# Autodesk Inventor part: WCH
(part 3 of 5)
hole "Díra1365" diameter "d12284" = 2.19608; stored, may be unused: countersink angle "d12288" = 90 deg, drill point angle "d12290" = 0 deg; dims "d12282" = 241, "d12283" = 153, "d12285" = 6, "d12286" = 4, "d12287" = 2, "d12289" = 8
hole "Díra1366" diameter "d12293" = 6.27451; stored, may be unused: countersink angle "d12297" = 90 deg, drill point angle "d12299" = 0 deg; dims "d12291" = 252, "d12292" = 153, "d12294" = 6, "d12295" = 4, "d12296" = 2, "d12298" = 8
hole "Díra1367" diameter "d12302" = 5.80392; stored, may be unused: countersink angle "d12306" = 90 deg, drill point angle "d12308" = 0 deg; dims "d12300" = 263, "d12301" = 153, "d12303" = 6, "d12304" = 4, "d12305" = 2, "d12307" = 8
hole "Díra1368" diameter "d12311" = 2.70588; stored, may be unused: countersink angle "d12315" = 90 deg, drill point angle "d12317" = 0 deg; dims "d12309" = 274, "d12310" = 153, "d12312" = 6, "d12313" = 4, "d12314" = 2, "d12316" = 8
hole "Díra1369" diameter "d12320" = 1.09804; stored, may be unused: countersink angle "d12324" = 90 deg, drill point angle "d12326" = 0 deg; dims "d12318" = 285, "d12319" = 153, "d12321" = 6, "d12322" = 4, "d12323" = 2, "d12325" = 8
hole "Díra1370" diameter "d12329" = 2.07843; stored, may be unused: countersink angle "d12333" = 90 deg, drill point angle "d12335" = 0 deg; dims "d12327" = 296, "d12328" = 153, "d12330" = 6, "d12331" = 4, "d12332" = 2, "d12334" = 8
hole "Díra1371" diameter "d12338" = 1.01961; stored, may be unused: countersink angle "d12342" = 90 deg, drill point angle "d12344" = 0 deg; dims "d12336" = 307, "d12337" = 153, "d12339" = 6, "d12340" = 4, "d12341" = 2, "d12343" = 8
hole "Díra1372" diameter "d12347" = 0.75817; stored, may be unused: countersink angle "d12351" = 90 deg, drill point angle "d12353" = 0 deg; dims "d12345" = 318, "d12346" = 153, "d12348" = 6, "d12349" = 4, "d12350" = 2, "d12352" = 8
hole "Díra1373" diameter "d12356" = 0.82353; stored, may be unused: countersink angle "d12360" = 90 deg, drill point angle "d12362" = 0 deg; dims "d12354" = 329, "d12355" = 153, "d12357" = 6, "d12358" = 4, "d12359" = 2, "d12361" = 8
hole "Díra1374" diameter "d12365" = 1.33333; stored, may be unused: countersink angle "d12369" = 90 deg, drill point angle "d12371" = 0 deg; dims "d12363" = 340, "d12364" = 153, "d12366" = 6, "d12367" = 4, "d12368" = 2, "d12370" = 8
hole "Díra1375" diameter "d12374" = 1.88235; stored, may be unused: countersink angle "d12378" = 90 deg, drill point angle "d12380" = 0 deg; dims "d12372" = 351, "d12373" = 153, "d12375" = 6, "d12376" = 4, "d12377" = 2, "d12379" = 8
hole "Díra1376" diameter "d12383" = 3.41176; stored, may be unused: countersink angle "d12387" = 90 deg, drill point angle "d12389" = 0 deg; dims "d12381" = 10, "d12382" = 164, "d12384" = 6, "d12385" = 4, "d12386" = 2, "d12388" = 8
hole "Díra1377" diameter "d12392" = 3.17647; stored, may be unused: countersink angle "d12396" = 90 deg, drill point angle "d12398" = 0 deg; dims "d12390" = 21, "d12391" = 164, "d12393" = 6, "d12394" = 4, "d12395" = 2, "d12397" = 8
hole "Díra1378" diameter "d12401" = 2.27451; stored, may be unused: countersink angle "d12405" = 90 deg, drill point angle "d12407" = 0 deg; dims "d12399" = 32, "d12400" = 164, "d12402" = 6, "d12403" = 4, "d12404" = 2, "d12406" = 8
hole "Díra1379" diameter "d12410" = 4.78431; stored, may be unused: countersink angle "d12414" = 90 deg, drill point angle "d12416" = 0 deg; dims "d12408" = 43, "d12409" = 164, "d12411" = 6, "d12412" = 4, "d12413" = 2, "d12415" = 8
hole "Díra1380" diameter "d12419" = 8.82353; stored, may be unused: countersink angle "d12423" = 90 deg, drill point angle "d12425" = 0 deg; dims "d12417" = 54, "d12418" = 164, "d12420" = 6, "d12421" = 4, "d12422" = 2, "d12424" = 8
hole "Díra1381" diameter "d12428" = 5.64706; stored, may be unused: countersink angle "d12432" = 90 deg, drill point angle "d12434" = 0 deg; dims "d12426" = 65, "d12427" = 164, "d12429" = 6, "d12430" = 4, "d12431" = 2, "d12433" = 8
hole "Díra1382" diameter "d12437" = 10; stored, may be unused: countersink angle "d12441" = 90 deg, drill point angle "d12443" = 0 deg; dims "d12435" = 76, "d12436" = 164, "d12438" = 6, "d12439" = 4, "d12440" = 2, "d12442" = 8
hole "Díra1383" diameter "d12446" = 8.54902; stored, may be unused: countersink angle "d12450" = 90 deg, drill point angle "d12452" = 0 deg; dims "d12444" = 87, "d12445" = 164, "d12447" = 6, "d12448" = 4, "d12449" = 2, "d12451" = 8
hole "Díra1384" diameter "d12455" = 2.47059; stored, may be unused: countersink angle "d12459" = 90 deg, drill point angle "d12461" = 0 deg; dims "d12453" = 98, "d12454" = 164, "d12456" = 6, "d12457" = 4, "d12458" = 2, "d12460" = 8
hole "Díra1385" diameter "d12464" = 2.94118; stored, may be unused: countersink angle "d12468" = 90 deg, drill point angle "d12470" = 0 deg; dims "d12462" = 109, "d12463" = 164, "d12465" = 6, "d12466" = 4, "d12467" = 2, "d12469" = 8
hole "Díra1386" diameter "d12473" = 4; stored, may be unused: countersink angle "d12477" = 90 deg, drill point angle "d12479" = 0 deg; dims "d12471" = 120, "d12472" = 164, "d12474" = 6, "d12475" = 4, "d12476" = 2, "d12478" = 8
hole "Díra1387" diameter "d12482" = 5.41177; stored, may be unused: countersink angle "d12486" = 90 deg, drill point angle "d12488" = 0 deg; dims "d12480" = 131, "d12481" = 164, "d12483" = 6, "d12484" = 4, "d12485" = 2, "d12487" = 8
hole "Díra1388" diameter "d12491" = 5.41177; stored, may be unused: countersink angle "d12495" = 90 deg, drill point angle "d12497" = 0 deg; dims "d12489" = 142, "d12490" = 164, "d12492" = 6, "d12493" = 4, "d12494" = 2, "d12496" = 8
hole "Díra1389" diameter "d12500" = 5.29412; stored, may be unused: countersink angle "d12504" = 90 deg, drill point angle "d12506" = 0 deg; dims "d12498" = 153, "d12499" = 164, "d12501" = 6, "d12502" = 4, "d12503" = 2, "d12505" = 8
hole "Díra1390" diameter "d12509" = 6.66667; stored, may be unused: countersink angle "d12513" = 90 deg, drill point angle "d12515" = 0 deg; dims "d12507" = 164, "d12508" = 164, "d12510" = 6, "d12511" = 4, "d12512" = 2, "d12514" = 8
hole "Díra1391" diameter "d12518" = 5.05882; stored, may be unused: countersink angle "d12522" = 90 deg, drill point angle "d12524" = 0 deg; dims "d12516" = 175, "d12517" = 164, "d12519" = 6, "d12520" = 4, "d12521" = 2, "d12523" = 8
hole "Díra1392" diameter "d12527" = 5.4902; stored, may be unused: countersink angle "d12531" = 90 deg, drill point angle "d12533" = 0 deg; dims "d12525" = 186, "d12526" = 164, "d12528" = 6, "d12529" = 4, "d12530" = 2, "d12532" = 8
hole "Díra1393" diameter "d12536" = 6.7451; stored, may be unused: countersink angle "d12540" = 90 deg, drill point angle "d12542" = 0 deg; dims "d12534" = 197, "d12535" = 164, "d12537" = 6, "d12538" = 4, "d12539" = 2, "d12541" = 8
hole "Díra1394" diameter "d12545" = 6.07843; stored, may be unused: countersink angle "d12549" = 90 deg, drill point angle "d12551" = 0 deg; dims "d12543" = 208, "d12544" = 164, "d12546" = 6, "d12547" = 4, "d12548" = 2, "d12550" = 8
hole "Díra1395" diameter "d12554" = 6.78431; stored, may be unused: countersink angle "d12558" = 90 deg, drill point angle "d12560" = 0 deg; dims "d12552" = 219, "d12553" = 164, "d12555" = 6, "d12556" = 4, "d12557" = 2, "d12559" = 8
hole "Díra1396" diameter "d12563" = 6.5098; stored, may be unused: countersink angle "d12567" = 90 deg, drill point angle "d12569" = 0 deg; dims "d12561" = 230, "d12562" = 164, "d12564" = 6, "d12565" = 4, "d12566" = 2, "d12568" = 8
hole "Díra1397" diameter "d12572" = 5.68628; stored, may be unused: countersink angle "d12576" = 90 deg, drill point angle "d12578" = 0 deg; dims "d12570" = 241, "d12571" = 164, "d12573" = 6, "d12574" = 4, "d12575" = 2, "d12577" = 8
hole "Díra1398" diameter "d12581" = 4.48366; stored, may be unused: countersink angle "d12585" = 90 deg, drill point angle "d12587" = 0 deg; dims "d12579" = 252, "d12580" = 164, "d12582" = 6, "d12583" = 4, "d12584" = 2, "d12586" = 8
hole "Díra1399" diameter "d12590" = 3.37255; stored, may be unused: countersink angle "d12594" = 90 deg, drill point angle "d12596" = 0 deg; dims "d12588" = 263, "d12589" = 164, "d12591" = 6, "d12592" = 4, "d12593" = 2, "d12595" = 8
hole "Díra1400" diameter "d12599" = 1.72549; stored, may be unused: countersink angle "d12603" = 90 deg, drill point angle "d12605" = 0 deg; dims "d12597" = 274, "d12598" = 164, "d12600" = 6, "d12601" = 4, "d12602" = 2, "d12604" = 8
hole "Díra1401" diameter "d12608" = 0.07843; stored, may be unused: countersink angle "d12612" = 90 deg, drill point angle "d12614" = 0 deg; dims "d12606" = 318, "d12607" = 164, "d12609" = 6, "d12610" = 4, "d12611" = 2, "d12613" = 8
hole "Díra1402" diameter "d12617" = 0.5098; stored, may be unused: countersink angle "d12621" = 90 deg, drill point angle "d12623" = 0 deg; dims "d12615" = 329, "d12616" = 164, "d12618" = 6, "d12619" = 4, "d12620" = 2, "d12622" = 8
hole "Díra1403" diameter "d12626" = 0.78431; stored, may be unused: countersink angle "d12630" = 90 deg, drill point angle "d12632" = 0 deg; dims "d12624" = 340, "d12625" = 164, "d12627" = 6, "d12628" = 4, "d12629" = 2, "d12631" = 8
hole "Díra1404" diameter "d12635" = 1.33333; stored, may be unused: countersink angle "d12639" = 90 deg, drill point angle "d12641" = 0 deg; dims "d12633" = 351, "d12634" = 164, "d12636" = 6, "d12637" = 4, "d12638" = 2, "d12640" = 8
hole "Díra1405" diameter "d12644" = 3.80392; stored, may be unused: countersink angle "d12648" = 90 deg, drill point angle "d12650" = 0 deg; dims "d12642" = 10, "d12643" = 175, "d12645" = 6, "d12646" = 4, "d12647" = 2, "d12649" = 8
hole "Díra1406" diameter "d12653" = 3.76471; stored, may be unused: countersink angle "d12657" = 90 deg, drill point angle "d12659" = 0 deg; dims "d12651" = 21, "d12652" = 175, "d12654" = 6, "d12655" = 4, "d12656" = 2, "d12658" = 8
hole "Díra1407" diameter "d12662" = 2.7451; stored, may be unused: countersink angle "d12666" = 90 deg, drill point angle "d12668" = 0 deg; dims "d12660" = 32, "d12661" = 175, "d12663" = 6, "d12664" = 4, "d12665" = 2, "d12667" = 8
hole "Díra1408" diameter "d12671" = 3.60784; stored, may be unused: countersink angle "d12675" = 90 deg, drill point angle "d12677" = 0 deg; dims "d12669" = 43, "d12670" = 175, "d12672" = 6, "d12673" = 4, "d12674" = 2, "d12676" = 8
hole "Díra1409" diameter "d12680" = 6.47059; stored, may be unused: countersink angle "d12684" = 90 deg, drill point angle "d12686" = 0 deg, countersink angle "d14007" = 90 deg; dims "d12678" = 54, "d12679" = 175, "d12681" = 6, "d12682" = 4, "d12683" = 2, "d12685" = 8
hole "Díra1410" diameter "d12689" = 8.43137; stored, may be unused: countersink angle "d12693" = 90 deg, drill point angle "d12695" = 0 deg; dims "d12687" = 65, "d12688" = 175, "d12690" = 6, "d12691" = 4, "d12692" = 2, "d12694" = 8, "d16117" = 318
hole "Díra1411" diameter "d12698" = 10; stored, may be unused: countersink angle "d12702" = 90 deg, drill point angle "d12704" = 0 deg; dims "d12696" = 76, "d12697" = 175, "d12699" = 6, "d12700" = 4, "d12701" = 2, "d12703" = 8
hole "Díra1412" diameter "d12707" = 6.66667; stored, may be unused: countersink angle "d12711" = 90 deg, drill point angle "d12713" = 0 deg; dims "d12705" = 87, "d12706" = 175, "d12708" = 6, "d12709" = 4, "d12710" = 2, "d12712" = 8
hole "Díra1413" diameter "d12716" = 2.19608; stored, may be unused: countersink angle "d12720" = 90 deg, drill point angle "d12722" = 0 deg; dims "d12714" = 98, "d12715" = 175, "d12717" = 6, "d12718" = 4, "d12719" = 2, "d12721" = 8
hole "Díra1414" diameter "d12725" = 3.4902; stored, may be unused: countersink angle "d12729" = 90 deg, drill point angle "d12731" = 0 deg; dims "d12723" = 109, "d12724" = 175, "d12726" = 6, "d12727" = 4, "d12728" = 2, "d12730" = 8
hole "Díra1415" diameter "d12734" = 3.13726; stored, may be unused: countersink angle "d12738" = 90 deg, drill point angle "d12740" = 0 deg; dims "d12732" = 120, "d12733" = 175, "d12735" = 6, "d12736" = 4, "d12737" = 2, "d12739" = 8
hole "Díra1416" diameter "d12743" = 1.84314; stored, may be unused: countersink angle "d12747" = 90 deg, drill point angle "d12749" = 0 deg; dims "d12741" = 131, "d12742" = 175, "d12744" = 6, "d12745" = 4, "d12746" = 2, "d12748" = 8
hole "Díra1417" diameter "d12752" = 1.01961; stored, may be unused: countersink angle "d12756" = 90 deg, drill point angle "d12758" = 0 deg; dims "d12750" = 142, "d12751" = 175, "d12753" = 6, "d12754" = 4, "d12755" = 2, "d12757" = 8
hole "Díra1418" diameter "d12761" = 0.5098; stored, may be unused: countersink angle "d12765" = 90 deg, drill point angle "d12767" = 0 deg; dims "d12759" = 153, "d12760" = 175, "d12762" = 6, "d12763" = 4, "d12764" = 2, "d12766" = 8
hole "Díra1419" diameter "d12770" = 1.60784; stored, may be unused: countersink angle "d12774" = 90 deg, drill point angle "d12776" = 0 deg; dims "d12768" = 164, "d12769" = 175, "d12771" = 6, "d12772" = 4, "d12773" = 2, "d12775" = 8
hole "Díra1420" diameter "d12779" = 5.80392; stored, may be unused: countersink angle "d12783" = 90 deg, drill point angle "d12785" = 0 deg; dims "d12777" = 175, "d12778" = 175, "d12780" = 6, "d12781" = 4, "d12782" = 2, "d12784" = 8
hole "Díra1421" diameter "d12788" = 2.15686; stored, may be unused: countersink angle "d12792" = 90 deg, drill point angle "d12794" = 0 deg; dims "d12786" = 186, "d12787" = 175, "d12789" = 6, "d12790" = 4, "d12791" = 2, "d12793" = 8
hole "Díra1422" diameter "d12797" = 1.92157; stored, may be unused: countersink angle "d12801" = 90 deg, drill point angle "d12803" = 0 deg; dims "d12795" = 197, "d12796" = 175, "d12798" = 6, "d12799" = 4, "d12800" = 2, "d12802" = 8
hole "Díra1423" diameter "d12806" = 0.90196; stored, may be unused: countersink angle "d12810" = 90 deg, drill point angle "d12812" = 0 deg; dims "d12804" = 208, "d12805" = 175, "d12807" = 6, "d12808" = 4, "d12809" = 2, "d12811" = 8
hole "Díra1424" diameter "d12815" = 1.01961; stored, may be unused: countersink angle "d12819" = 90 deg, drill point angle "d12821" = 0 deg; dims "d12813" = 219, "d12814" = 175, "d12816" = 6, "d12817" = 4, "d12818" = 2, "d12820" = 8
hole "Díra1425" diameter "d12824" = 1.92157; stored, may be unused: countersink angle "d12828" = 90 deg, drill point angle "d12830" = 0 deg; dims "d12822" = 230, "d12823" = 175, "d12825" = 6, "d12826" = 4, "d12827" = 2, "d12829" = 8
hole "Díra1426" diameter "d12833" = 4.82353; stored, may be unused: countersink angle "d12837" = 90 deg, drill point angle "d12839" = 0 deg; dims "d12831" = 241, "d12832" = 175, "d12834" = 6, "d12835" = 4, "d12836" = 2, "d12838" = 8
hole "Díra1427" diameter "d12842" = 1.52941; stored, may be unused: countersink angle "d12846" = 90 deg, drill point angle "d12848" = 0 deg; dims "d12840" = 252, "d12841" = 175, "d12843" = 6, "d12844" = 4, "d12845" = 2, "d12847" = 8
hole "Díra1428" diameter "d12851" = 0.78431; stored, may be unused: countersink angle "d12855" = 90 deg, drill point angle "d12857" = 0 deg; dims "d12849" = 263, "d12850" = 175, "d12852" = 6, "d12853" = 4, "d12854" = 2, "d12856" = 8
hole "Díra1429" diameter "d12860" = 0.39216; stored, may be unused: countersink angle "d12864" = 90 deg, drill point angle "d12866" = 0 deg; dims "d12858" = 274, "d12859" = 175, "d12861" = 6, "d12862" = 4, "d12863" = 2, "d12865" = 8
hole "Díra1430" diameter "d12869" = 0.27451; stored, may be unused: countersink angle "d12873" = 90 deg, drill point angle "d12875" = 0 deg; dims "d12867" = 307, "d12868" = 175, "d12870" = 6, "d12871" = 4, "d12872" = 2, "d12874" = 8
hole "Díra1431" diameter "d12878" = 0.15686; stored, may be unused: countersink angle "d12882" = 90 deg, drill point angle "d12884" = 0 deg; dims "d12876" = 340, "d12877" = 175, "d12879" = 6, "d12880" = 4, "d12881" = 2, "d12883" = 8
hole "Díra1432" diameter "d12887" = 0.90196; stored, may be unused: countersink angle "d12891" = 90 deg, drill point angle "d12893" = 0 deg; dims "d12885" = 351, "d12886" = 175, "d12888" = 6, "d12889" = 4, "d12890" = 2, "d12892" = 8
hole "Díra1433" diameter "d12896" = 3.29412; stored, may be unused: countersink angle "d12900" = 90 deg, drill point angle "d12902" = 0 deg; dims "d12894" = 10, "d12895" = 186, "d12897" = 6, "d12898" = 4, "d12899" = 2, "d12901" = 8
hole "Díra1434" diameter "d12905" = 3.17647; stored, may be unused: countersink angle "d12909" = 90 deg, drill point angle "d12911" = 0 deg; dims "d12903" = 21, "d12904" = 186, "d12906" = 6, "d12907" = 4, "d12908" = 2, "d12910" = 8
hole "Díra1435" diameter "d12914" = 3.21569; stored, may be unused: countersink angle "d12918" = 90 deg, drill point angle "d12920" = 0 deg; dims "d12912" = 32, "d12913" = 186, "d12915" = 6, "d12916" = 4, "d12917" = 2, "d12919" = 8
hole "Díra1436" diameter "d12923" = 3.84314; stored, may be unused: countersink angle "d12927" = 90 deg, drill point angle "d12929" = 0 deg; dims "d12921" = 43, "d12922" = 186, "d12924" = 6, "d12925" = 4, "d12926" = 2, "d12928" = 8
hole "Díra1437" diameter "d12932" = 3.01961; stored, may be unused: countersink angle "d12936" = 90 deg, drill point angle "d12938" = 0 deg; dims "d12930" = 54, "d12931" = 186, "d12933" = 6, "d12934" = 4, "d12935" = 2, "d12937" = 8
hole "Díra1438" diameter "d12941" = 6.39216; stored, may be unused: countersink angle "d12945" = 90 deg, drill point angle "d12947" = 0 deg; dims "d12939" = 65, "d12940" = 186, "d12942" = 6, "d12943" = 4, "d12944" = 2, "d12946" = 8
hole "Díra1439" diameter "d12950" = 7.52941; stored, may be unused: countersink angle "d12954" = 90 deg, drill point angle "d12956" = 0 deg; dims "d12948" = 76, "d12949" = 186, "d12951" = 6, "d12952" = 4, "d12953" = 2, "d12955" = 8
hole "Díra1440" diameter "d12959" = 2.77124; stored, may be unused: countersink angle "d12963" = 90 deg, drill point angle "d12965" = 0 deg; dims "d12957" = 87, "d12958" = 186, "d12960" = 6, "d12961" = 4, "d12962" = 2, "d12964" = 8
hole "Díra1441" diameter "d12968" = 2.66667; stored, may be unused: countersink angle "d12972" = 90 deg, drill point angle "d12974" = 0 deg; dims "d12966" = 98, "d12967" = 186, "d12969" = 6, "d12970" = 4, "d12971" = 2, "d12973" = 8
hole "Díra1442" diameter "d12977" = 4.27451; stored, may be unused: countersink angle "d12981" = 90 deg, drill point angle "d12983" = 0 deg; dims "d12975" = 109, "d12976" = 186, "d12978" = 6, "d12979" = 4, "d12980" = 2, "d12982" = 8
hole "Díra1443" diameter "d12986" = 4.35294; stored, may be unused: countersink angle "d12990" = 90 deg, drill point angle "d12992" = 0 deg; dims "d12984" = 120, "d12985" = 186, "d12987" = 6, "d12988" = 4, "d12989" = 2, "d12991" = 8
hole "Díra1444" diameter "d12995" = 2.39216; stored, may be unused: countersink angle "d12999" = 90 deg, drill point angle "d13001" = 0 deg; dims "d12993" = 131, "d12994" = 186, "d12996" = 6, "d12997" = 4, "d12998" = 2, "d13000" = 8
hole "Díra1445" diameter "d13004" = 0.5098; stored, may be unused: countersink angle "d13008" = 90 deg, drill point angle "d13010" = 0 deg; dims "d13002" = 142, "d13003" = 186, "d13005" = 6, "d13006" = 4, "d13007" = 2, "d13009" = 8
hole "Díra1446" diameter "d13013" = 0.07843; stored, may be unused: countersink angle "d13017" = 90 deg, drill point angle "d13019" = 0 deg; dims "d13011" = 153, "d13012" = 186, "d13014" = 6, "d13015" = 4, "d13016" = 2, "d13018" = 8
hole "Díra1447" diameter "d13022" = 0.15686; stored, may be unused: countersink angle "d13026" = 90 deg, drill point angle "d13028" = 0 deg; dims "d13020" = 164, "d13021" = 186, "d13023" = 6, "d13024" = 4, "d13025" = 2, "d13027" = 8
hole "Díra1448" diameter "d13031" = 1.64706; stored, may be unused: countersink angle "d13035" = 90 deg, drill point angle "d13037" = 0 deg; dims "d13029" = 175, "d13030" = 186, "d13032" = 6, "d13033" = 4, "d13034" = 2, "d13036" = 8
hole "Díra1449" diameter "d13040" = 4; stored, may be unused: countersink angle "d13044" = 90 deg, drill point angle "d13046" = 0 deg; dims "d13038" = 186, "d13039" = 186, "d13041" = 6, "d13042" = 4, "d13043" = 2, "d13045" = 8
hole "Díra1450" diameter "d13049" = 2.90196; stored, may be unused: countersink angle "d13053" = 90 deg, drill point angle "d13055" = 0 deg; dims "d13047" = 197, "d13048" = 186, "d13050" = 6, "d13051" = 4, "d13052" = 2, "d13054" = 8
hole "Díra1451" diameter "d13058" = 0.27451; stored, may be unused: countersink angle "d13062" = 90 deg, drill point angle "d13064" = 0 deg; dims "d13056" = 208, "d13057" = 186, "d13059" = 6, "d13060" = 4, "d13061" = 2, "d13063" = 8
hole "Díra1452" diameter "d13067" = 3.52941; stored, may be unused: countersink angle "d13071" = 90 deg, drill point angle "d13073" = 0 deg; dims "d13065" = 230, "d13066" = 186, "d13068" = 6, "d13069" = 4, "d13070" = 2, "d13072" = 8
hole "Díra1453" diameter "d13076" = 3.76471; stored, may be unused: countersink angle "d13080" = 90 deg, drill point angle "d13082" = 0 deg; dims "d13074" = 241, "d13075" = 186, "d13077" = 6, "d13078" = 4, "d13079" = 2, "d13081" = 8
hole "Díra1454" diameter "d13085" = 0.78431; stored, may be unused: countersink angle "d13089" = 90 deg, drill point angle "d13091" = 0 deg; dims "d13083" = 252, "d13084" = 186, "d13086" = 6, "d13087" = 4, "d13088" = 2, "d13090" = 8
hole "Díra1455" diameter "d13094" = 0.43137; stored, may be unused: countersink angle "d13098" = 90 deg, drill point angle "d13100" = 0 deg; dims "d13092" = 263, "d13093" = 186, "d13095" = 6, "d13096" = 4, "d13097" = 2, "d13099" = 8
hole "Díra1456" diameter "d13103" = 1.01961; stored, may be unused: countersink angle "d13107" = 90 deg, drill point angle "d13109" = 0 deg; dims "d13101" = 274, "d13102" = 186, "d13104" = 6, "d13105" = 4, "d13106" = 2, "d13108" = 8
hole "Díra1457" diameter "d13112" = 0.19608; stored, may be unused: countersink angle "d13116" = 90 deg, drill point angle "d13118" = 0 deg; dims "d13110" = 285, "d13111" = 186, "d13113" = 6, "d13114" = 4, "d13115" = 2, "d13117" = 8
hole "Díra1458" diameter "d13121" = 0.31372; stored, may be unused: countersink angle "d13125" = 90 deg, drill point angle "d13127" = 0 deg; dims "d13119" = 296, "d13120" = 186, "d13122" = 6, "d13123" = 4, "d13124" = 2, "d13126" = 8
hole "Díra1459" diameter "d13130" = 3.01961; stored, may be unused: countersink angle "d13134" = 90 deg, drill point angle "d13136" = 0 deg; dims "d13128" = 307, "d13129" = 186, "d13131" = 6, "d13132" = 4, "d13133" = 2, "d13135" = 8
hole "Díra1460" diameter "d13139" = 2.19608; stored, may be unused: countersink angle "d13143" = 90 deg, drill point angle "d13145" = 0 deg; dims "d13137" = 318, "d13138" = 186, "d13140" = 6, "d13141" = 4, "d13142" = 2, "d13144" = 8
hole "Díra1461" diameter "d13148" = 3.4902; stored, may be unused: countersink angle "d13152" = 90 deg, drill point angle "d13154" = 0 deg; dims "d13146" = 10, "d13147" = 197, "d13149" = 6, "d13150" = 4, "d13151" = 2, "d13153" = 8
hole "Díra1462" diameter "d13157" = 3.37255; stored, may be unused: countersink angle "d13161" = 90 deg, drill point angle "d13163" = 0 deg; dims "d13155" = 21, "d13156" = 197, "d13158" = 6, "d13159" = 4, "d13160" = 2, "d13162" = 8
hole "Díra1463" diameter "d13166" = 3.01961; stored, may be unused: countersink angle "d13170" = 90 deg, drill point angle "d13172" = 0 deg; dims "d13164" = 32, "d13165" = 197, "d13167" = 6, "d13168" = 4, "d13169" = 2, "d13171" = 8
hole "Díra1464" diameter "d13175" = 4.39216; stored, may be unused: countersink angle "d13179" = 90 deg, drill point angle "d13181" = 0 deg; dims "d13173" = 43, "d13174" = 197, "d13176" = 6, "d13177" = 4, "d13178" = 2, "d13180" = 8
hole "Díra1465" diameter "d13184" = 2.58824; stored, may be unused: countersink angle "d13188" = 90 deg, drill point angle "d13190" = 0 deg; dims "d13182" = 54, "d13183" = 197, "d13185" = 6, "d13186" = 4, "d13187" = 2, "d13189" = 8
hole "Díra1466" diameter "d13193" = 1.13725; stored, may be unused: countersink angle "d13197" = 90 deg, drill point angle "d13199" = 0 deg; dims "d13191" = 65, "d13192" = 197, "d13194" = 6, "d13195" = 4, "d13196" = 2, "d13198" = 8
hole "Díra1467" diameter "d13202" = 2.5098; stored, may be unused: countersink angle "d13206" = 90 deg, drill point angle "d13208" = 0 deg; dims "d13200" = 76, "d13201" = 197, "d13203" = 6, "d13204" = 4, "d13205" = 2, "d13207" = 8
hole "Díra1468" diameter "d13211" = 4.66667; stored, may be unused: countersink angle "d13215" = 90 deg, drill point angle "d13217" = 0 deg; dims "d13209" = 87, "d13210" = 197, "d13212" = 6, "d13213" = 4, "d13214" = 2, "d13216" = 8
hole "Díra1469" diameter "d13220" = 3.37255; stored, may be unused: countersink angle "d13224" = 90 deg, drill point angle "d13226" = 0 deg; dims "d13218" = 98, "d13219" = 197, "d13221" = 6, "d13222" = 4, "d13223" = 2, "d13225" = 8
hole "Díra1470" diameter "d13229" = 4.90196; stored, may be unused: countersink angle "d13233" = 90 deg, drill point angle "d13235" = 0 deg; dims "d13227" = 109, "d13228" = 197, "d13230" = 6, "d13231" = 4, "d13232" = 2, "d13234" = 8
hole "Díra1471" diameter "d13238" = 3.01961; stored, may be unused: countersink angle "d13242" = 90 deg, drill point angle "d13244" = 0 deg; dims "d13236" = 120, "d13237" = 197, "d13239" = 6, "d13240" = 4, "d13241" = 2, "d13243" = 8
hole "Díra1472" diameter "d13247" = 1.41177; stored, may be unused: countersink angle "d13251" = 90 deg, drill point angle "d13253" = 0 deg; dims "d13245" = 131, "d13246" = 197, "d13248" = 6, "d13249" = 4, "d13250" = 2, "d13252" = 8
hole "Díra1473" diameter "d13256" = 1.2549; stored, may be unused: countersink angle "d13260" = 90 deg, drill point angle "d13262" = 0 deg; dims "d13254" = 142, "d13255" = 197, "d13257" = 6, "d13258" = 4, "d13259" = 2, "d13261" = 8
hole "Díra1474" diameter "d13265" = 1.84314; stored, may be unused: countersink angle "d13269" = 90 deg, drill point angle "d13271" = 0 deg; dims "d13263" = 153, "d13264" = 197, "d13266" = 6, "d13267" = 4, "d13268" = 2, "d13270" = 8
hole "Díra1475" diameter "d13274" = 1.13725; stored, may be unused: countersink angle "d13278" = 90 deg, drill point angle "d13280" = 0 deg; dims "d13272" = 164, "d13273" = 197, "d13275" = 6, "d13276" = 4, "d13277" = 2, "d13279" = 8
hole "Díra1476" diameter "d13283" = 0.47059; stored, may be unused: countersink angle "d13287" = 90 deg, drill point angle "d13289" = 0 deg; dims "d13281" = 175, "d13282" = 197, "d13284" = 6, "d13285" = 4, "d13286" = 2, "d13288" = 8
hole "Díra1477" diameter "d13292" = 1.72549; stored, may be unused: countersink angle "d13296" = 90 deg, drill point angle "d13298" = 0 deg; dims "d13290" = 186, "d13291" = 197, "d13293" = 6, "d13294" = 4, "d13295" = 2, "d13297" = 8
hole "Díra1478" diameter "d13301" = 2.94118; stored, may be unused: countersink angle "d13305" = 90 deg, drill point angle "d13307" = 0 deg; dims "d13299" = 197, "d13300" = 197, "d13302" = 6, "d13303" = 4, "d13304" = 2, "d13306" = 8
hole "Díra1479" diameter "d13310" = 0.66667; stored, may be unused: countersink angle "d13314" = 90 deg, drill point angle "d13316" = 0 deg; dims "d13308" = 208, "d13309" = 197, "d13311" = 6, "d13312" = 4, "d13313" = 2, "d13315" = 8
hole "Díra1480" diameter "d13319" = 0.5098; stored, may be unused: countersink angle "d13323" = 90 deg, drill point angle "d13325" = 0 deg; dims "d13317" = 219, "d13318" = 197, "d13320" = 6, "d13321" = 4, "d13322" = 2, "d13324" = 8
hole "Díra1481" diameter "d13328" = 2.5098; stored, may be unused: countersink angle "d13332" = 90 deg, drill point angle "d13334" = 0 deg; dims "d13326" = 230, "d13327" = 197, "d13329" = 6, "d13330" = 4, "d13331" = 2, "d13333" = 8
hole "Díra1482" diameter "d13337" = 1.2549; stored, may be unused: countersink angle "d13341" = 90 deg, drill point angle "d13343" = 0 deg; dims "d13335" = 241, "d13336" = 197, "d13338" = 6, "d13339" = 4, "d13340" = 2, "d13342" = 8
hole "Díra1483" diameter "d13346" = 1.01961; stored, may be unused: countersink angle "d13350" = 90 deg, drill point angle "d13352" = 0 deg; dims "d13344" = 252, "d13345" = 197, "d13347" = 6, "d13348" = 4, "d13349" = 2, "d13351" = 8
hole "Díra1484" diameter "d13355" = 1.80392; stored, may be unused: countersink angle "d13359" = 90 deg, drill point angle "d13361" = 0 deg; dims "d13353" = 263, "d13354" = 197, "d13356" = 6, "d13357" = 4, "d13358" = 2, "d13360" = 8
hole "Díra1485" diameter "d13364" = 2.90196; stored, may be unused: countersink angle "d13368" = 90 deg, drill point angle "d13370" = 0 deg; dims "d13362" = 274, "d13363" = 197, "d13365" = 6, "d13366" = 4, "d13367" = 2, "d13369" = 8
hole "Díra1486" diameter "d13373" = 1.05882; stored, may be unused: countersink angle "d13377" = 90 deg, drill point angle "d13379" = 0 deg; dims "d13371" = 285, "d13372" = 197, "d13374" = 6, "d13375" = 4, "d13376" = 2, "d13378" = 8
hole "Díra1487" diameter "d13382" = 0.15686; stored, may be unused: countersink angle "d13386" = 90 deg, drill point angle "d13388" = 0 deg; dims "d13380" = 329, "d13381" = 197, "d13383" = 6, "d13384" = 4, "d13385" = 2, "d13387" = 8
hole "Díra1488" diameter "d13391" = 0.07843; stored, may be unused: countersink angle "d13395" = 90 deg, drill point angle "d13397" = 0 deg; dims "d13389" = 340, "d13390" = 197, "d13392" = 6, "d13393" = 4, "d13394" = 2, "d13396" = 8
hole "Díra1489" diameter "d13400" = 0.07843; stored, may be unused: countersink angle "d13404" = 90 deg, drill point angle "d13406" = 0 deg; dims "d13398" = 351, "d13399" = 197, "d13401" = 6, "d13402" = 4, "d13403" = 2, "d13405" = 8
hole "Díra1490" diameter "d13409" = 3.56863; stored, may be unused: countersink angle "d13413" = 90 deg, drill point angle "d13415" = 0 deg; dims "d13407" = 10, "d13408" = 208, "d13410" = 6, "d13411" = 4, "d13412" = 2, "d13414" = 8
hole "Díra1491" diameter "d13418" = 3.56863; stored, may be unused: countersink angle "d13422" = 90 deg, drill point angle "d13424" = 0 deg; dims "d13416" = 21, "d13417" = 208, "d13419" = 6, "d13420" = 4, "d13421" = 2, "d13423" = 8
hole "Díra1492" diameter "d13427" = 3.4902; stored, may be unused: countersink angle "d13431" = 90 deg, drill point angle "d13433" = 0 deg; dims "d13425" = 32, "d13426" = 208, "d13428" = 6, "d13429" = 4, "d13430" = 2, "d13432" = 8
hole "Díra1493" diameter "d13436" = 4.35294; stored, may be unused: countersink angle "d13440" = 90 deg, drill point angle "d13442" = 0 deg; dims "d13434" = 43, "d13435" = 208, "d13437" = 6, "d13438" = 4, "d13439" = 2, "d13441" = 8
hole "Díra1494" diameter "d13445" = 3.21569; stored, may be unused: countersink angle "d13449" = 90 deg, drill point angle "d13451" = 0 deg; dims "d13443" = 54, "d13444" = 208, "d13446" = 6, "d13447" = 4, "d13448" = 2, "d13450" = 8
hole "Díra1495" diameter "d13454" = 1.05882; stored, may be unused: countersink angle "d13458" = 90 deg, drill point angle "d13460" = 0 deg; dims "d13452" = 65, "d13453" = 208, "d13455" = 6, "d13456" = 4, "d13457" = 2, "d13459" = 8
hole "Díra1496" diameter "d13463" = 2.70588; stored, may be unused: countersink angle "d13467" = 90 deg, drill point angle "d13469" = 0 deg; dims "d13461" = 76, "d13462" = 208, "d13464" = 6, "d13465" = 4, "d13466" = 2, "d13468" = 8
hole "Díra1497" diameter "d13472" = 4.90196; stored, may be unused: countersink angle "d13476" = 90 deg, drill point angle "d13478" = 0 deg; dims "d13470" = 87, "d13471" = 208, "d13473" = 6, "d13474" = 4, "d13475" = 2, "d13477" = 8
hole "Díra1498" diameter "d13481" = 5.09804; stored, may be unused: countersink angle "d13485" = 90 deg, drill point angle "d13487" = 0 deg; dims "d13479" = 98, "d13480" = 208, "d13482" = 6, "d13483" = 4, "d13484" = 2, "d13486" = 8
hole "Díra1499" diameter "d13490" = 5.09804; stored, may be unused: countersink angle "d13494" = 90 deg, drill point angle "d13496" = 0 deg; dims "d13488" = 109, "d13489" = 208, "d13491" = 6, "d13492" = 4, "d13493" = 2, "d13495" = 8
hole "Díra1500" diameter "d13499" = 1.84314; stored, may be unused: countersink angle "d13503" = 90 deg, drill point angle "d13505" = 0 deg; dims "d13497" = 120, "d13498" = 208, "d13500" = 6, "d13501" = 4, "d13502" = 2, "d13504" = 8
hole "Díra1501" diameter "d13508" = 1.45098; stored, may be unused: countersink angle "d13512" = 90 deg, drill point angle "d13514" = 0 deg; dims "d13506" = 131, "d13507" = 208, "d13509" = 6, "d13510" = 4, "d13511" = 2, "d13513" = 8
hole "Díra1502" diameter "d13517" = 1.41177; stored, may be unused: countersink angle "d13521" = 90 deg, drill point angle "d13523" = 0 deg; dims "d13515" = 142, "d13516" = 208, "d13518" = 6, "d13519" = 4, "d13520" = 2, "d13522" = 8
hole "Díra1503" diameter "d13526" = 1.88235; stored, may be unused: countersink angle "d13530" = 90 deg, drill point angle "d13532" = 0 deg; dims "d13524" = 153, "d13525" = 208, "d13527" = 6, "d13528" = 4, "d13529" = 2, "d13531" = 8
hole "Díra1504" diameter "d13535" = 2.66667; stored, may be unused: countersink angle "d13539" = 90 deg, drill point angle "d13541" = 0 deg; dims "d13533" = 164, "d13534" = 208, "d13536" = 6, "d13537" = 4, "d13538" = 2, "d13540" = 8
hole "Díra1505" diameter "d13544" = 1.45098; stored, may be unused: countersink angle "d13548" = 90 deg, drill point angle "d13550" = 0 deg; dims "d13542" = 175, "d13543" = 208, "d13545" = 6, "d13546" = 4, "d13547" = 2, "d13549" = 8
hole "Díra1506" diameter "d13553" = 1.4902; stored, may be unused: countersink angle "d13557" = 90 deg, drill point angle "d13559" = 0 deg; dims "d13551" = 186, "d13552" = 208, "d13554" = 6, "d13555" = 4, "d13556" = 2, "d13558" = 8
hole "Díra1507" diameter "d13562" = 2.78431; stored, may be unused: countersink angle "d13566" = 90 deg, drill point angle "d13568" = 0 deg; dims "d13560" = 197, "d13561" = 208, "d13563" = 6, "d13564" = 4, "d13565" = 2, "d13567" = 8
hole "Díra1508" diameter "d13571" = 0.5098; stored, may be unused: countersink angle "d13575" = 90 deg, drill point angle "d13577" = 0 deg; dims "d13569" = 208, "d13570" = 208, "d13572" = 6, "d13573" = 4, "d13574" = 2, "d13576" = 8
hole "Díra1509" diameter "d13580" = 1.13725; stored, may be unused: countersink angle "d13584" = 90 deg, drill point angle "d13586" = 0 deg; dims "d13578" = 219, "d13579" = 208, "d13581" = 6, "d13582" = 4, "d13583" = 2, "d13585" = 8
hole "Díra1510" diameter "d13589" = 1.72549; stored, may be unused: countersink angle "d13593" = 90 deg, drill point angle "d13595" = 0 deg; dims "d13587" = 230, "d13588" = 208, "d13590" = 6, "d13591" = 4, "d13592" = 2, "d13594" = 8
hole "Díra1511" diameter "d13598" = 2.82353; stored, may be unused: countersink angle "d13602" = 90 deg, drill point angle "d13604" = 0 deg; dims "d13596" = 241, "d13597" = 208, "d13599" = 6, "d13600" = 4, "d13601" = 2, "d13603" = 8
hole "Díra1512" diameter "d13607" = 4.66667; stored, may be unused: countersink angle "d13611" = 90 deg, drill point angle "d13613" = 0 deg; dims "d13605" = 252, "d13606" = 208, "d13608" = 6, "d13609" = 4, "d13610" = 2, "d13612" = 8
hole "Díra1513" diameter "d13616" = 4.23529; stored, may be unused: countersink angle "d13620" = 90 deg, drill point angle "d13622" = 0 deg; dims "d13614" = 263, "d13615" = 208, "d13617" = 6, "d13618" = 4, "d13619" = 2, "d13621" = 8
hole "Díra1514" diameter "d13625" = 2.27451; stored, may be unused: countersink angle "d13629" = 90 deg, drill point angle "d13631" = 0 deg; dims "d13623" = 274, "d13624" = 208, "d13626" = 6, "d13627" = 4, "d13628" = 2, "d13630" = 8
hole "Díra1515" diameter "d13634" = 0.39216; stored, may be unused: countersink angle "d13638" = 90 deg, drill point angle "d13640" = 0 deg; dims "d13632" = 285, "d13633" = 208, "d13635" = 6, "d13636" = 4, "d13637" = 2, "d13639" = 8
hole "Díra1516" diameter "d13643" = 0.19608; stored, may be unused: countersink angle "d13647" = 90 deg, drill point angle "d13649" = 0 deg; dims "d13641" = 329, "d13642" = 208, "d13644" = 6, "d13645" = 4, "d13646" = 2, "d13648" = 8
hole "Díra1517" diameter "d13652" = 0.15686; stored, may be unused: countersink angle "d13656" = 90 deg, drill point angle "d13658" = 0 deg; dims "d13650" = 340, "d13651" = 208, "d13653" = 6, "d13654" = 4, "d13655" = 2, "d13657" = 8
hole "Díra1518" diameter "d13661" = 0.19608; stored, may be unused: countersink angle "d13665" = 90 deg, drill point angle "d13667" = 0 deg; dims "d13659" = 351, "d13660" = 208, "d13662" = 6, "d13663" = 4, "d13664" = 2, "d13666" = 8
hole "Díra1519" diameter "d13670" = 3.60784; stored, may be unused: countersink angle "d13674" = 90 deg, drill point angle "d13676" = 0 deg; dims "d13668" = 10, "d13669" = 219, "d13671" = 6, "d13672" = 4, "d13673" = 2, "d13675" = 8
hole "Díra1520" diameter "d13679" = 3.80392; stored, may be unused: countersink angle "d13683" = 90 deg, drill point angle "d13685" = 0 deg; dims "d13677" = 21, "d13678" = 219, "d13680" = 6, "d13681" = 4, "d13682" = 2, "d13684" = 8
hole "Díra1521" diameter "d13688" = 3.72549; stored, may be unused: countersink angle "d13692" = 90 deg, drill point angle "d13694" = 0 deg; dims "d13686" = 32, "d13687" = 219, "d13689" = 6, "d13690" = 4, "d13691" = 2, "d13693" = 8
hole "Díra1522" diameter "d13697" = 4.70588; stored, may be unused: countersink angle "d13701" = 90 deg, drill point angle "d13703" = 0 deg; dims "d13695" = 43, "d13696" = 219, "d13698" = 6, "d13699" = 4, "d13700" = 2, "d13702" = 8
hole "Díra1523" diameter "d13706" = 2.82353; stored, may be unused: countersink angle "d13710" = 90 deg, drill point angle "d13712" = 0 deg; dims "d13704" = 54, "d13705" = 219, "d13707" = 6, "d13708" = 4, "d13709" = 2, "d13711" = 8
hole "Díra1524" diameter "d13715" = 1.01961; stored, may be unused: countersink angle "d13719" = 90 deg, drill point angle "d13721" = 0 deg; dims "d13713" = 65, "d13714" = 219, "d13716" = 6, "d13717" = 4, "d13718" = 2, "d13720" = 8
hole "Díra1525" diameter "d13724" = 3.64706; stored, may be unused: countersink angle "d13728" = 90 deg, drill point angle "d13730" = 0 deg; dims "d13722" = 76, "d13723" = 219, "d13725" = 6, "d13726" = 4, "d13727" = 2, "d13729" = 8
hole "Díra1526" diameter "d13733" = 6; stored, may be unused: countersink angle "d13737" = 90 deg, drill point angle "d13739" = 0 deg; dims "d13731" = 87, "d13732" = 219, "d13734" = 6, "d13735" = 4, "d13736" = 2, "d13738" = 8
hole "Díra1527" diameter "d13742" = 5.84314; stored, may be unused: countersink angle "d13746" = 90 deg, drill point angle "d13748" = 0 deg; dims "d13740" = 98, "d13741" = 219, "d13743" = 6, "d13744" = 4, "d13745" = 2, "d13747" = 8
hole "Díra1528" diameter "d13751" = 4.23529; stored, may be unused: countersink angle "d13755" = 90 deg, drill point angle "d13757" = 0 deg; dims "d13749" = 109, "d13750" = 219, "d13752" = 6, "d13753" = 4, "d13754" = 2, "d13756" = 8
hole "Díra1529" diameter "d13760" = 2.70588; stored, may be unused: countersink angle "d13764" = 90 deg, drill point angle "d13766" = 0 deg; dims "d13758" = 120, "d13759" = 219, "d13761" = 6, "d13762" = 4, "d13763" = 2, "d13765" = 8
hole "Díra1530" diameter "d13769" = 5.68628; stored, may be unused: countersink angle "d13773" = 90 deg, drill point angle "d13775" = 0 deg; dims "d13767" = 131, "d13768" = 219, "d13770" = 6, "d13771" = 4, "d13772" = 2, "d13774" = 8
hole "Díra1531" diameter "d13778" = 6; stored, may be unused: countersink angle "d13782" = 90 deg, drill point angle "d13784" = 0 deg; dims "d13776" = 142, "d13777" = 219, "d13779" = 6, "d13780" = 4, "d13781" = 2, "d13783" = 8
hole "Díra1532" diameter "d13787" = 6.39216; stored, may be unused: countersink angle "d13791" = 90 deg, drill point angle "d13793" = 0 deg; dims "d13785" = 153, "d13786" = 219, "d13788" = 6, "d13789" = 4, "d13790" = 2, "d13792" = 8
hole "Díra1533" diameter "d13796" = 5.4902; stored, may be unused: countersink angle "d13800" = 90 deg, drill point angle "d13802" = 0 deg; dims "d13794" = 164, "d13795" = 219, "d13797" = 6, "d13798" = 4, "d13799" = 2, "d13801" = 8
hole "Díra1534" diameter "d13805" = 4.82353; stored, may be unused: countersink angle "d13809" = 90 deg, drill point angle "d13811" = 0 deg; dims "d13803" = 175, "d13804" = 219, "d13806" = 6, "d13807" = 4, "d13808" = 2, "d13810" = 8
hole "Díra1535" diameter "d13814" = 4.35294; stored, may be unused: countersink angle "d13818" = 90 deg, drill point angle "d13820" = 0 deg; dims "d13812" = 186, "d13813" = 219, "d13815" = 6, "d13816" = 4, "d13817" = 2, "d13819" = 8
hole "Díra1536" diameter "d13823" = 2.98039; stored, may be unused: countersink angle "d13827" = 90 deg, drill point angle "d13829" = 0 deg; dims "d13821" = 197, "d13822" = 219, "d13824" = 6, "d13825" = 4, "d13826" = 2, "d13828" = 8
hole "Díra1537" diameter "d13832" = 1.09804; stored, may be unused: countersink angle "d13836" = 90 deg, drill point angle "d13838" = 0 deg; dims "d13830" = 208, "d13831" = 219, "d13833" = 6, "d13834" = 4, "d13835" = 2, "d13837" = 8
hole "Díra1538" diameter "d13841" = 4.5098; stored, may be unused: countersink angle "d13845" = 90 deg, drill point angle "d13847" = 0 deg; dims "d13839" = 219, "d13840" = 219, "d13842" = 6, "d13843" = 4, "d13844" = 2, "d13846" = 8
hole "Díra1539" diameter "d13850" = 3.21569; stored, may be unused: countersink angle "d13854" = 90 deg, drill point angle "d13856" = 0 deg; dims "d13848" = 230, "d13849" = 219, "d13851" = 6, "d13852" = 4, "d13853" = 2, "d13855" = 8
hole "Díra1540" diameter "d13859" = 2.66667; stored, may be unused: countersink angle "d13863" = 90 deg, drill point angle "d13865" = 0 deg; dims "d13857" = 241, "d13858" = 219, "d13860" = 6, "d13861" = 4, "d13862" = 2, "d13864" = 8
hole "Díra1541" diameter "d13868" = 2.82353; stored, may be unused: countersink angle "d13872" = 90 deg, drill point angle "d13874" = 0 deg; dims "d13866" = 252, "d13867" = 219, "d13869" = 6, "d13870" = 4, "d13871" = 2, "d13873" = 8
hole "Díra1542" diameter "d13877" = 1.52941; stored, may be unused: countersink angle "d13881" = 90 deg, drill point angle "d13883" = 0 deg; dims "d13875" = 263, "d13876" = 219, "d13878" = 6, "d13879" = 4, "d13880" = 2, "d13882" = 8
hole "Díra1543" diameter "d13886" = 0.23529; stored, may be unused: countersink angle "d13890" = 90 deg, drill point angle "d13892" = 0 deg; dims "d13884" = 274, "d13885" = 219, "d13887" = 6, "d13888" = 4, "d13889" = 2, "d13891" = 8
hole "Díra1544" diameter "d13895" = 1.68628; stored, may be unused: countersink angle "d13899" = 90 deg, drill point angle "d13901" = 0 deg; dims "d13893" = 318, "d13894" = 219, "d13896" = 6, "d13897" = 4, "d13898" = 2, "d13900" = 8
hole "Díra1545" diameter "d13904" = 3.60784; stored, may be unused: countersink angle "d13908" = 90 deg, drill point angle "d13910" = 0 deg; dims "d13902" = 329, "d13903" = 219, "d13905" = 6, "d13906" = 4, "d13907" = 2, "d13909" = 8
hole "Díra1546" diameter "d13913" = 2.15686; stored, may be unused: countersink angle "d13917" = 90 deg, drill point angle "d13919" = 0 deg; dims "d13911" = 340, "d13912" = 219, "d13914" = 6, "d13915" = 4, "d13916" = 2, "d13918" = 8
hole "Díra1547" diameter "d13922" = 0.82353; stored, may be unused: countersink angle "d13926" = 90 deg, drill point angle "d13928" = 0 deg; dims "d13920" = 351, "d13921" = 219, "d13923" = 6, "d13924" = 4, "d13925" = 2, "d13927" = 8
hole "Díra1548" diameter "d13931" = 3.52941; stored, may be unused: countersink angle "d13935" = 90 deg, drill point angle "d13937" = 0 deg; dims "d13929" = 10, "d13930" = 230, "d13932" = 6, "d13933" = 4, "d13934" = 2, "d13936" = 8
hole "Díra1549" diameter "d13940" = 3.17647; stored, may be unused: countersink angle "d13944" = 90 deg, drill point angle "d13946" = 0 deg; dims "d13938" = 21, "d13939" = 230, "d13941" = 6, "d13942" = 4, "d13943" = 2, "d13945" = 8
hole "Díra1550" diameter "d13949" = 3.41176; stored, may be unused: countersink angle "d13953" = 90 deg, drill point angle "d13955" = 0 deg; dims "d13947" = 32, "d13948" = 230, "d13950" = 6, "d13951" = 4, "d13952" = 2, "d13954" = 8
hole "Díra1551" diameter "d13958" = 4.82353; stored, may be unused: countersink angle "d13962" = 90 deg, drill point angle "d13964" = 0 deg; dims "d13956" = 43, "d13957" = 230, "d13959" = 6, "d13960" = 4, "d13961" = 2, "d13963" = 8
hole "Díra1552" diameter "d13967" = 2.66667; stored, may be unused: countersink angle "d13971" = 90 deg, drill point angle "d13973" = 0 deg; dims "d13965" = 54, "d13966" = 230, "d13968" = 6, "d13969" = 4, "d13970" = 2, "d13972" = 8
hole "Díra1553" diameter "d13976" = 0.86275; stored, may be unused: countersink angle "d13980" = 90 deg, drill point angle "d13982" = 0 deg; dims "d13974" = 65, "d13975" = 230, "d13977" = 6, "d13978" = 4, "d13979" = 2, "d13981" = 8
hole "Díra1554" diameter "d13985" = 4.27451; stored, may be unused: countersink angle "d13989" = 90 deg, drill point angle "d13991" = 0 deg; dims "d13983" = 76, "d13984" = 230, "d13986" = 6, "d13987" = 4, "d13988" = 2, "d13990" = 8
hole "Díra1555" diameter "d13994" = 6.98039; stored, may be unused: countersink angle "d13998" = 90 deg, drill point angle "d14000" = 0 deg; dims "d13992" = 87, "d13993" = 230, "d13995" = 6, "d13996" = 4, "d13997" = 2, "d13999" = 8
hole "Díra1556" diameter "d14003" = 5.09804; stored, may be unused: countersink angle "d14007" = 90 deg, drill point angle "d14009" = 0 deg; dims "d14001" = 98, "d14002" = 230, "d14004" = 6, "d14005" = 4, "d14006" = 2, "d14008" = 8
hole "Díra1557" diameter "d14012" = 4.27451; stored, may be unused: countersink angle "d14016" = 90 deg, drill point angle "d14018" = 0 deg; dims "d14010" = 109, "d14011" = 230, "d14013" = 6, "d14014" = 4, "d14015" = 2, "d14017" = 8
hole "Díra1558" diameter "d14021" = 4.90196; stored, may be unused: countersink angle "d14025" = 90 deg, drill point angle "d14027" = 0 deg; dims "d14019" = 120, "d14020" = 230, "d14022" = 6, "d14023" = 4, "d14024" = 2, "d14026" = 8
hole "Díra1559" diameter "d14030" = 6.19608; stored, may be unused: countersink angle "d14034" = 90 deg, drill point angle "d14036" = 0 deg; dims "d14028" = 131, "d14029" = 230, "d14031" = 6, "d14032" = 4, "d14033" = 2, "d14035" = 8
hole "Díra1560" diameter "d14039" = 5.2549; stored, may be unused: countersink angle "d14043" = 90 deg, drill point angle "d14045" = 0 deg; dims "d14037" = 142, "d14038" = 230, "d14040" = 6, "d14041" = 4, "d14042" = 2, "d14044" = 8
hole "Díra1561" diameter "d14048" = 6.90196; stored, may be unused: countersink angle "d14052" = 90 deg, drill point angle "d14054" = 0 deg; dims "d14046" = 153, "d14047" = 230, "d14049" = 6, "d14050" = 4, "d14051" = 2, "d14053" = 8
hole "Díra1562" diameter "d14057" = 7.29412; stored, may be unused: countersink angle "d14061" = 90 deg, drill point angle "d14063" = 0 deg; dims "d14055" = 164, "d14056" = 230, "d14058" = 6, "d14059" = 4, "d14060" = 2, "d14062" = 8
hole "Díra1563" diameter "d14066" = 7.09804; stored, may be unused: countersink angle "d14070" = 90 deg, drill point angle "d14072" = 0 deg; dims "d14064" = 175, "d14065" = 230, "d14067" = 6, "d14068" = 4, "d14069" = 2, "d14071" = 8
hole "Díra1564" diameter "d14075" = 6.66667; stored, may be unused: countersink angle "d14079" = 90 deg, drill point angle "d14081" = 0 deg; dims "d14073" = 186, "d14074" = 230, "d14076" = 6, "d14077" = 4, "d14078" = 2, "d14080" = 8
hole "Díra1565" diameter "d14084" = 3.72549; stored, may be unused: countersink angle "d14088" = 90 deg, drill point angle "d14090" = 0 deg; dims "d14082" = 197, "d14083" = 230, "d14085" = 6, "d14086" = 4, "d14087" = 2, "d14089" = 8
hole "Díra1566" diameter "d14093" = 2.78431; stored, may be unused: countersink angle "d14097" = 90 deg, drill point angle "d14099" = 0 deg; dims "d14091" = 208, "d14092" = 230, "d14094" = 6, "d14095" = 4, "d14096" = 2, "d14098" = 8
hole "Díra1567" diameter "d14102" = 6.35294; stored, may be unused: countersink angle "d14106" = 90 deg, drill point angle "d14108" = 0 deg; dims "d14100" = 219, "d14101" = 230, "d14103" = 6, "d14104" = 4, "d14105" = 2, "d14107" = 8
hole "Díra1568" diameter "d14111" = 6.71895; stored, may be unused: countersink angle "d14115" = 90 deg, drill point angle "d14117" = 0 deg; dims "d14109" = 230, "d14110" = 230, "d14112" = 6, "d14113" = 4, "d14114" = 2, "d14116" = 8
hole "Díra1569" diameter "d14120" = 7.37255; stored, may be unused: countersink angle "d14124" = 90 deg, drill point angle "d14126" = 0 deg; dims "d14118" = 241, "d14119" = 230, "d14121" = 6, "d14122" = 4, "d14123" = 2, "d14125" = 8
hole "Díra1570" diameter "d14129" = 8.54902; stored, may be unused: countersink angle "d14133" = 90 deg, drill point angle "d14135" = 0 deg; dims "d14127" = 252, "d14128" = 230, "d14130" = 6, "d14131" = 4, "d14132" = 2, "d14134" = 8
hole "Díra1571" diameter "d14138" = 7.68628; stored, may be unused: countersink angle "d14142" = 90 deg, drill point angle "d14144" = 0 deg; dims "d14136" = 263, "d14137" = 230, "d14139" = 6, "d14140" = 4, "d14141" = 2, "d14143" = 8
hole "Díra1572" diameter "d14147" = 4.82353; stored, may be unused: countersink angle "d14151" = 90 deg, drill point angle "d14153" = 0 deg; dims "d14145" = 274, "d14146" = 230, "d14148" = 6, "d14149" = 4, "d14150" = 2, "d14152" = 8
hole "Díra1573" diameter "d14156" = 1.33333; stored, may be unused: countersink angle "d14160" = 90 deg, drill point angle "d14162" = 0 deg; dims "d14154" = 318, "d14155" = 230, "d14157" = 6, "d14158" = 4, "d14159" = 2, "d14161" = 8
hole "Díra1574" diameter "d14165" = 4.58824; stored, may be unused: countersink angle "d14169" = 90 deg, drill point angle "d14171" = 0 deg; dims "d14163" = 329, "d14164" = 230, "d14166" = 6, "d14167" = 4, "d14168" = 2, "d14170" = 8
hole "Díra1575" diameter "d14174" = 3.72549; stored, may be unused: countersink angle "d14178" = 90 deg, drill point angle "d14180" = 0 deg; dims "d14172" = 340, "d14173" = 230, "d14175" = 6, "d14176" = 4, "d14177" = 2, "d14179" = 8
hole "Díra1576" diameter "d14183" = 1.33333; stored, may be unused: countersink angle "d14187" = 90 deg, drill point angle "d14189" = 0 deg; dims "d14181" = 351, "d14182" = 230, "d14184" = 6, "d14185" = 4, "d14186" = 2, "d14188" = 8
hole "Díra1577" diameter "d14192" = 3.4902; stored, may be unused: countersink angle "d14196" = 90 deg, drill point angle "d14198" = 0 deg; dims "d14190" = 10, "d14191" = 241, "d14193" = 6, "d14194" = 4, "d14195" = 2, "d14197" = 8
